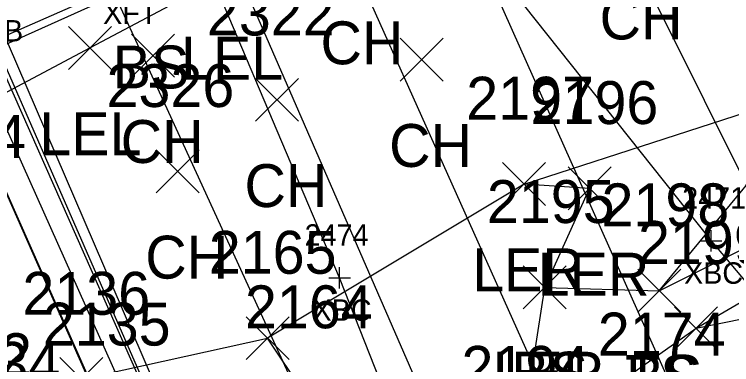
# Model space of a CAD drawing. Extents: x 1504228 to 1506103, y 437717 to 440106.
# Drawn here: x 1505201.55 to 1505234.96, y 438165.45 to 438181.79 of the extents above; entities that cross this region are included whole.
import ezdxf

# ---------------------------------------------------------------- set-up
doc = ezdxf.new("R2010")
doc.units = 0
for name, color, linetype in [('B_A', 7, 'Continuous'), ('B_I', 7, 'Continuous'), ('B_TIC', 7, 'Continuous'), ('BB', 7, 'Continuous'), ('BDC', 7, 'Continuous'), ('BELB', 7, 'Continuous'), ('BF', 7, 'Continuous'), ('BFT', 7, 'Continuous'), ('BR', 7, 'Continuous'), ('L_A', 7, 'Continuous'), ('L_I', 7, 'Continuous'), ('L_TIC', 7, 'Continuous'), ('LARO', 7, 'Continuous'), ('LAWE', 7, 'Continuous'), ('LELB', 7, 'Continuous')]:
    doc.layers.add(name, color=color, linetype=linetype)

msp = doc.modelspace()

# ---------------------------------------------------------------- linework, layer by layer
at = {"layer": 'B_TIC'}
for p, q in [((1505234.005, 438171.224), (1505234.081, 438171.224)), ((1505216.703, 438169.498), (1505216.778, 438169.498))]:
    msp.add_line(p, q, dxfattribs=at)
for points in [[(1505234.002, 438170.724), (1505234.002, 438171.724)], [(1505233.502, 438171.224), (1505234.502, 438171.224)], [(1505216.699, 438168.998), (1505216.699, 438169.998)], [(1505216.199, 438169.498), (1505217.199, 438169.498)]]:
    msp.add_lwpolyline(points, dxfattribs=at)
at = {"layer": 'BB'}
for points in [[(1505245.599, 438153.876), (1505225.746, 438193.733)], [(1505238.272, 438150.725), (1505220.207, 438191.242)], [(1505233.176, 438148.763), (1505215.135, 438189.07)], [(1505228.522, 438145.721), (1505210.599, 438186.937)], [(1505224.014, 438143.855), (1505205.318, 438184.714)], [(1505218.208, 438141.011), (1505200.34, 438182.519)]]:
    msp.add_lwpolyline(points, dxfattribs=at)
at = {"layer": 'BDC'}
msp.add_lwpolyline([(1505177.99, 438228.719), (1505178.876, 438228.45), (1505180.438, 438226.195), (1505192.555, 438198.391), (1505198.96, 438183.8), (1505208.446, 438162.36), (1505217.081, 438142.744), (1505218.046, 438139.452)], dxfattribs=at)
at = {"layer": 'BELB'}
for points in [[(1505189.093, 438232.07), (1505202.074, 438213.317), (1505217.089, 438192.519), (1505234.002, 438171.224), (1505249.231, 438153.134)], [(1505179.043, 438228.597), (1505180.553, 438226.219), (1505192.716, 438198.549), (1505199.089, 438184.038), (1505208.574, 438162.333), (1505217.312, 438142.723), (1505218.32, 438139.52)], [(1505227.121, 438143.057), (1505216.699, 438169.498), (1505208.631, 438188.54), (1505199.093, 438209.718)]]:
    msp.add_lwpolyline(points, dxfattribs=at)
at = {"layer": 'BF'}
for points in [[(1505177.99, 438228.719), (1505179.189, 438225.504), (1505178.468, 438225.175), (1505190.518, 438197.862), (1505196.85, 438183.23), (1505206.498, 438161.372), (1505215.121, 438141.85), (1505216.234, 438142.341), (1505217.418, 438139.282), (1505218.046, 438139.452)], [(1505178.471, 438225.17), (1505190.541, 438197.836), (1505196.878, 438183.176), (1505206.558, 438161.349), (1505215.066, 438141.897)]]:
    msp.add_lwpolyline(points, dxfattribs=at)
at = {"layer": 'BFT'}
msp.add_lwpolyline([(1505252.998, 438208.079), (1505252.263, 438206.145), (1505250.763, 438202.931), (1505232.133, 438194.68), (1505231.606, 438194.296), (1505223.29, 438190.638), (1505216.076, 438187.39), (1505206.938, 438183.343), (1505196.92, 438178.938), (1505191.516, 438180.897), (1505192.342, 438183.974)], dxfattribs=at)
at = {"layer": 'BR'}
msp.add_lwpolyline([(1505179.189, 438225.504), (1505191.7, 438198.009), (1505198.057, 438183.407), (1505207.736, 438161.768), (1505216.234, 438142.341)], dxfattribs=at)
at = {"layer": 'L_TIC'}
for points in [[(1505204.073, 438179.218), (1505206.073, 438181.218)], [(1505206.073, 438179.218), (1505204.073, 438181.218)], [(1505207.011, 438178.856), (1505209.011, 438180.856)], [(1505209.011, 438178.856), (1505207.011, 438180.856)], [(1505219.515, 438178.671), (1505221.515, 438180.671)], [(1505221.515, 438178.671), (1505219.515, 438180.671)], [(1505212.778, 438176.801), (1505214.778, 438178.801)], [(1505214.778, 438176.801), (1505212.778, 438178.801)], [(1505208.158, 438173.465), (1505210.158, 438175.465)], [(1505210.158, 438173.465), (1505208.158, 438175.465)], [(1505224.288, 438172.876), (1505226.288, 438174.876)], [(1505226.288, 438172.876), (1505224.288, 438174.876)], [(1505227.34, 438172.672), (1505229.34, 438174.672)], [(1505229.34, 438172.672), (1505227.34, 438174.672)], [(1505225.248, 438168.057), (1505227.248, 438170.057)], [(1505227.248, 438168.057), (1505225.248, 438170.057)], [(1505225.248, 438168.057), (1505227.248, 438170.057)], [(1505227.248, 438168.057), (1505225.248, 438170.057)], [(1505230.587, 438167.903), (1505232.587, 438169.903)], [(1505232.587, 438167.903), (1505230.587, 438169.903)], [(1505230.587, 438167.903), (1505232.587, 438169.903)], [(1505232.587, 438167.903), (1505230.587, 438169.903)], [(1505232.297, 438166.151), (1505234.297, 438168.151)], [(1505234.297, 438166.151), (1505232.297, 438168.151)], [(1505232.297, 438166.151), (1505234.297, 438168.151)], [(1505234.297, 438166.151), (1505232.297, 438168.151)], [(1505212.345, 438165.691), (1505214.345, 438167.691)], [(1505214.345, 438165.691), (1505212.345, 438167.691)], [(1505212.345, 438165.691), (1505214.345, 438167.691)], [(1505214.345, 438165.691), (1505212.345, 438167.691)], [(1505203.671, 438163.78), (1505205.671, 438165.78)], [(1505205.671, 438163.78), (1505203.671, 438165.78)]]:
    msp.add_lwpolyline(points, dxfattribs=at)
at = {"layer": 'LARO'}
for points in [[(1505257.789, 438202.997), (1505250.211, 438200.467), (1505241.258, 438195.88), (1505230.318, 438190.813), (1505221.077, 438187.488), (1505211.673, 438183.738), (1505205.073, 438180.218), (1505196.112, 438175.447), (1505190.999, 438172.732), (1505182.993, 438174.698), (1505180.265, 438174.662)], [(1505225.066, 438161.326), (1505226.248, 438169.057), (1505228.34, 438173.672), (1505225.288, 438173.876), (1505239.482, 438178.474), (1505243.528, 438176.585), (1505251.729, 438176.792), (1505258.116, 438181.066), (1505273.159, 438181.503), (1505274.516, 438179.171), (1505287.419, 438180.921)], [(1505225.288, 438173.876), (1505213.345, 438166.691)], [(1505195.084, 438151.064), (1505194.566, 438158.722), (1505193.725, 438163.089), (1505204.671, 438164.78), (1505213.345, 438166.691)], [(1505211.067, 438140.867), (1505213.787, 438148.55), (1505214.791, 438151.569), (1505216.536, 438157.155), (1505215.03, 438164.15), (1505213.345, 438166.691)]]:
    msp.add_lwpolyline(points, dxfattribs=at)
at = {"layer": 'LAWE'}
msp.add_lwpolyline([(1505191.715, 438146.002), (1505202.906, 438148.803), (1505214.791, 438151.569), (1505218.42, 438155.881), (1505225.066, 438161.326), (1505233.297, 438167.151), (1505239.085, 438170.522), (1505246.461, 438173.024), (1505251.729, 438176.792), (1505260.319, 438178.7), (1505267.708, 438179.756), (1505273.159, 438181.503), (1505280.716, 438184.584), (1505293.606, 438188.67), (1505306.287, 438194.997), (1505316.183, 438195.439), (1505329.815, 438205.572), (1505347.823, 438213.433)], dxfattribs=at)
at = {"layer": 'LELB'}
for points in [[(1505365.146, 438316.099), (1505353.966, 438296.236), (1505341.915, 438275.153), (1505332.016, 438262.134), (1505323.954, 438252.628), (1505313.563, 438242.629), (1505305.646, 438236.558), (1505295.746, 438229.78), (1505286.64, 438224.685), (1505273.677, 438216.738), (1505262.485, 438213.279), (1505253.251, 438208.207), (1505250.962, 438202.759), (1505231.919, 438194.06), (1505223.449, 438190.476), (1505215.829, 438187.003), (1505207.689, 438183.331), (1505196.859, 438178.456)], [(1505233.297, 438167.151), (1505239.043, 438168.314), (1505249.04, 438172.836), (1505251.629, 438175.015), (1505261.788, 438177.035), (1505269.325, 438179.089), (1505274.516, 438179.171), (1505268.419, 438175.277), (1505270.919, 438173.353), (1505279.4, 438176.776), (1505285.106, 438180.489)], [(1505231.587, 438168.903), (1505239.482, 438178.474)], [(1505226.248, 438169.057), (1505231.587, 438168.903), (1505238.686, 438172.451), (1505243.528, 438176.585)]]:
    msp.add_lwpolyline(points, dxfattribs=at)

# ---------------------------------------------------------------- texts
at = {"layer": 'B_A'}
for s, p in [('XFT', (1505205.683, 438181.343)), ('XBIB', (1505198.911, 438180.519)), ('XBC', (1505232.738, 438169.224)), ('XBC', (1505215.435, 438167.498))]:
    msp.add_text(s, height=1, dxfattribs=at).set_placement(p)
at = {"layer": 'B_I'}
for s, p in [('2471', (1505232.655, 438172.724)), ('2474', (1505215.069, 438170.998))]:
    msp.add_text(s, height=1, dxfattribs=at).set_placement(p)
at = {"layer": 'L_A'}
for s, p in [('CH', (1505228.805, 438180.615)), ('CH', (1505215.807, 438179.457)), ('LEL', (1505209.311, 438178.738)), ('BS', (1505206.13, 438178.331)), ('LEL', (1505202.71, 438175.218)), ('CH', (1505206.5, 438174.856)), ('CH', (1505219.003, 438174.671)), ('CH', (1505212.266, 438172.801)), ('CH', (1505207.646, 438169.465)), ('LER', (1505222.871, 438168.876)), ('LER', (1505225.923, 438168.672)), ('LER', (1505223.831, 438164.057)), ('BS', (1505224.689, 438164.057)), ('TS', (1505229.997, 438163.903)), ('BS', (1505230.028, 438163.903))]:
    msp.add_text(s, height=2, dxfattribs=at).set_placement(p)
at = {"layer": 'L_I'}
for s, p in [('2322', (1505210.518, 438180.801)), ('2326', (1505205.843, 438177.465)), ('2197', (1505222.595, 438176.876)), ('2196', (1505225.592, 438176.672)), ('1814', (1505196.148, 438175.094)), ('2195', (1505223.556, 438172.057)), ('2195', (1505223.556, 438172.057)), ('2198', (1505228.894, 438171.903)), ('2198', (1505228.894, 438171.903)), ('2199', (1505230.596, 438170.151)), ('2199', (1505230.596, 438170.151)), ('2165', (1505210.605, 438169.691)), ('2165', (1505210.605, 438169.691)), ('2136', (1505201.923, 438167.78)), ('2164', (1505212.289, 438167.15)), ('2135', (1505202.876, 438166.344)), ('2174', (1505228.724, 438165.88)), ('2132', (1505196.421, 438164.918)), ('2134', (1505197.736, 438164.515)), ('2194', (1505222.373, 438164.326)), ('2194', (1505222.373, 438164.326))]:
    msp.add_text(s, height=2, dxfattribs=at).set_placement(p)

doc.saveas('drawing.dxf')
